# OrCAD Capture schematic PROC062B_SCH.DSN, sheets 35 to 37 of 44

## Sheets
35 34.SERDES & DISPLAY INTERFACE: size C; title: SERDES & DISPLAY INTERFACE
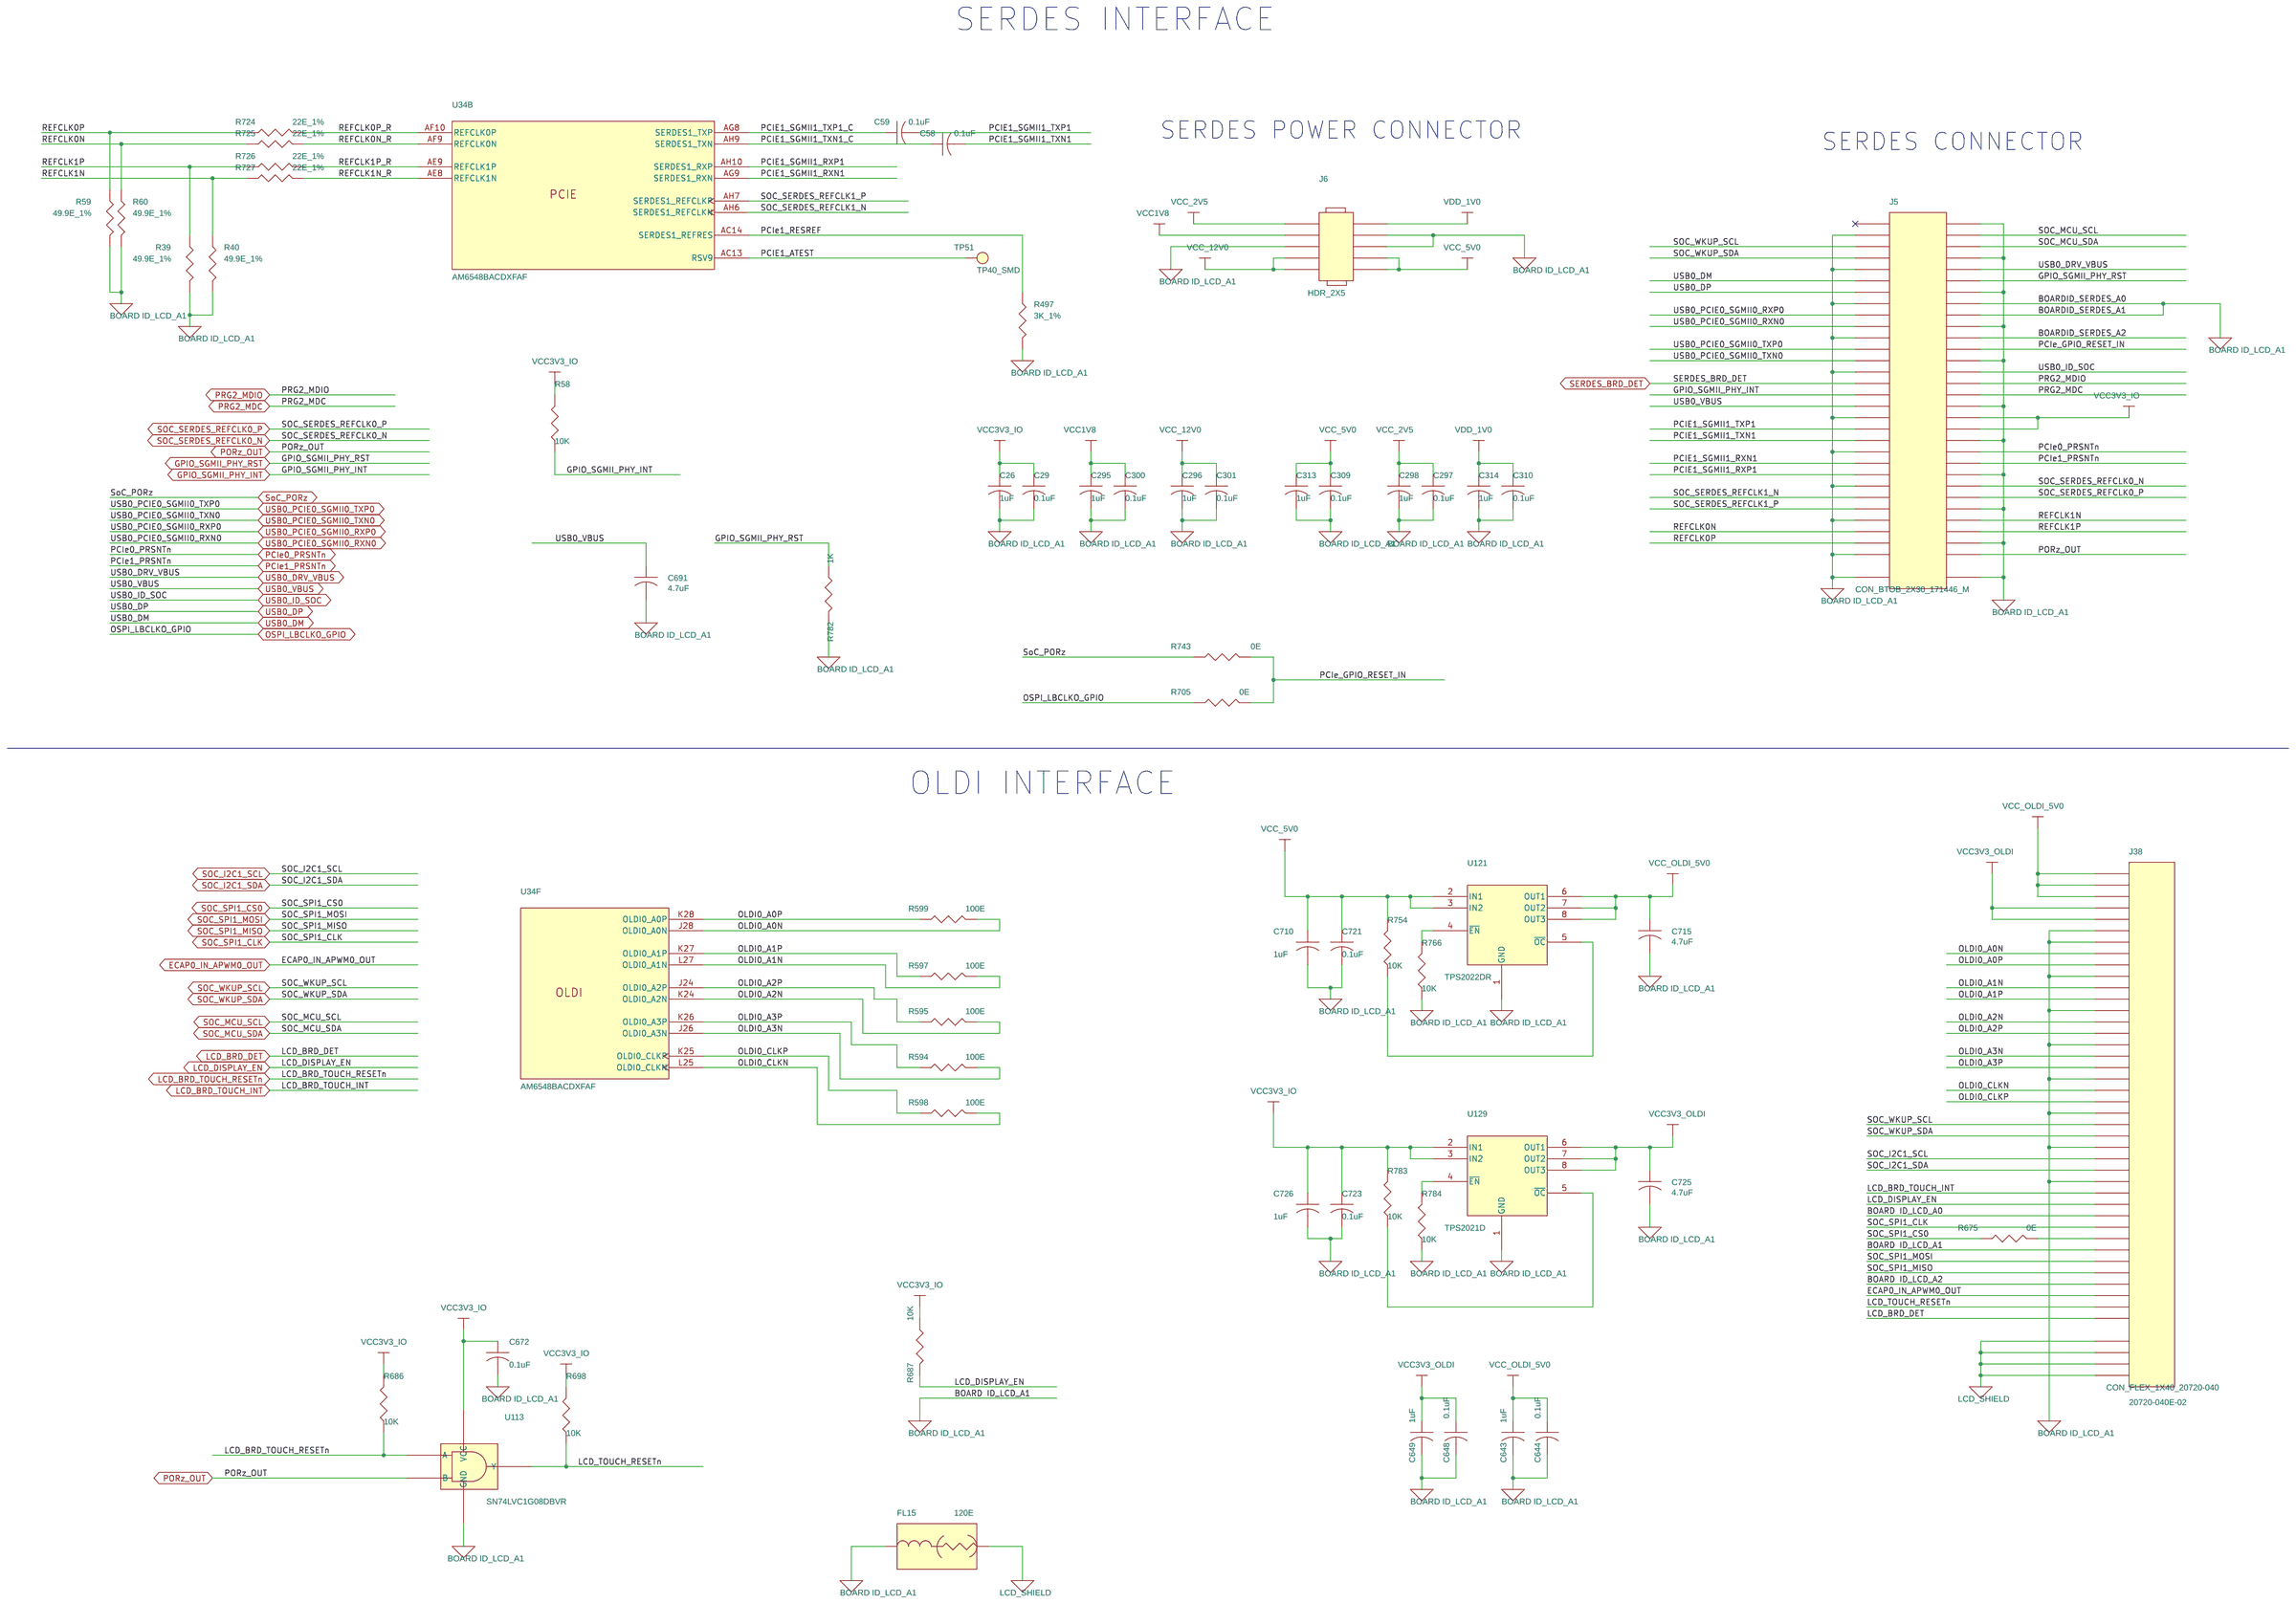
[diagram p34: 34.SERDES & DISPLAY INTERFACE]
36 36.ETHERNET PHY CLOCK BUFFER: size C; title: ETHERNET PHY CLOCK GENERATOR
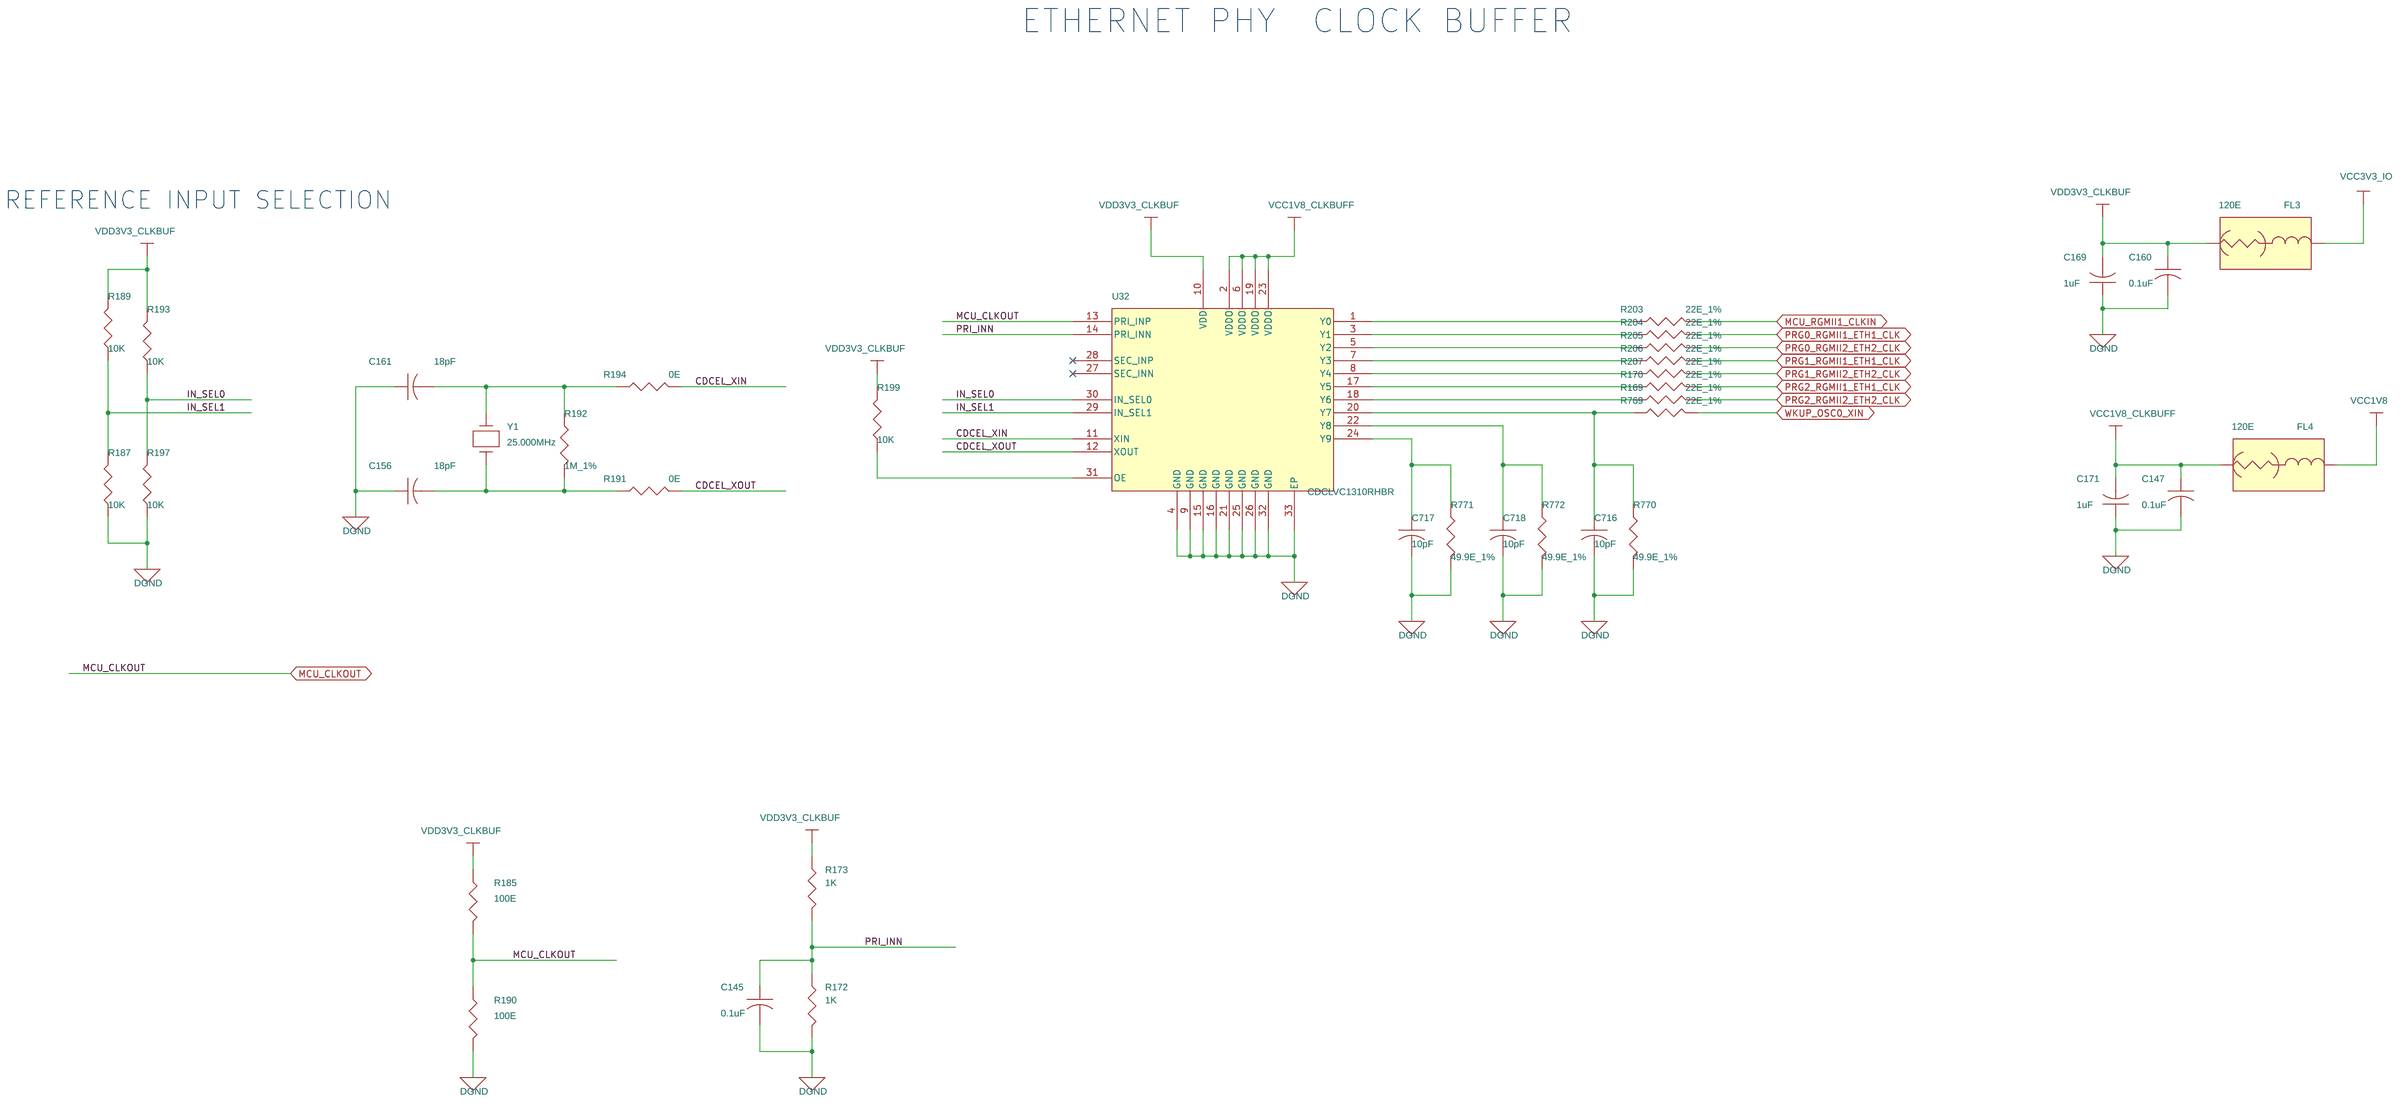
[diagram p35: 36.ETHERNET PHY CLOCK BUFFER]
37 37. ETHERNET LED's: size C; title: ETHERNET LEDs
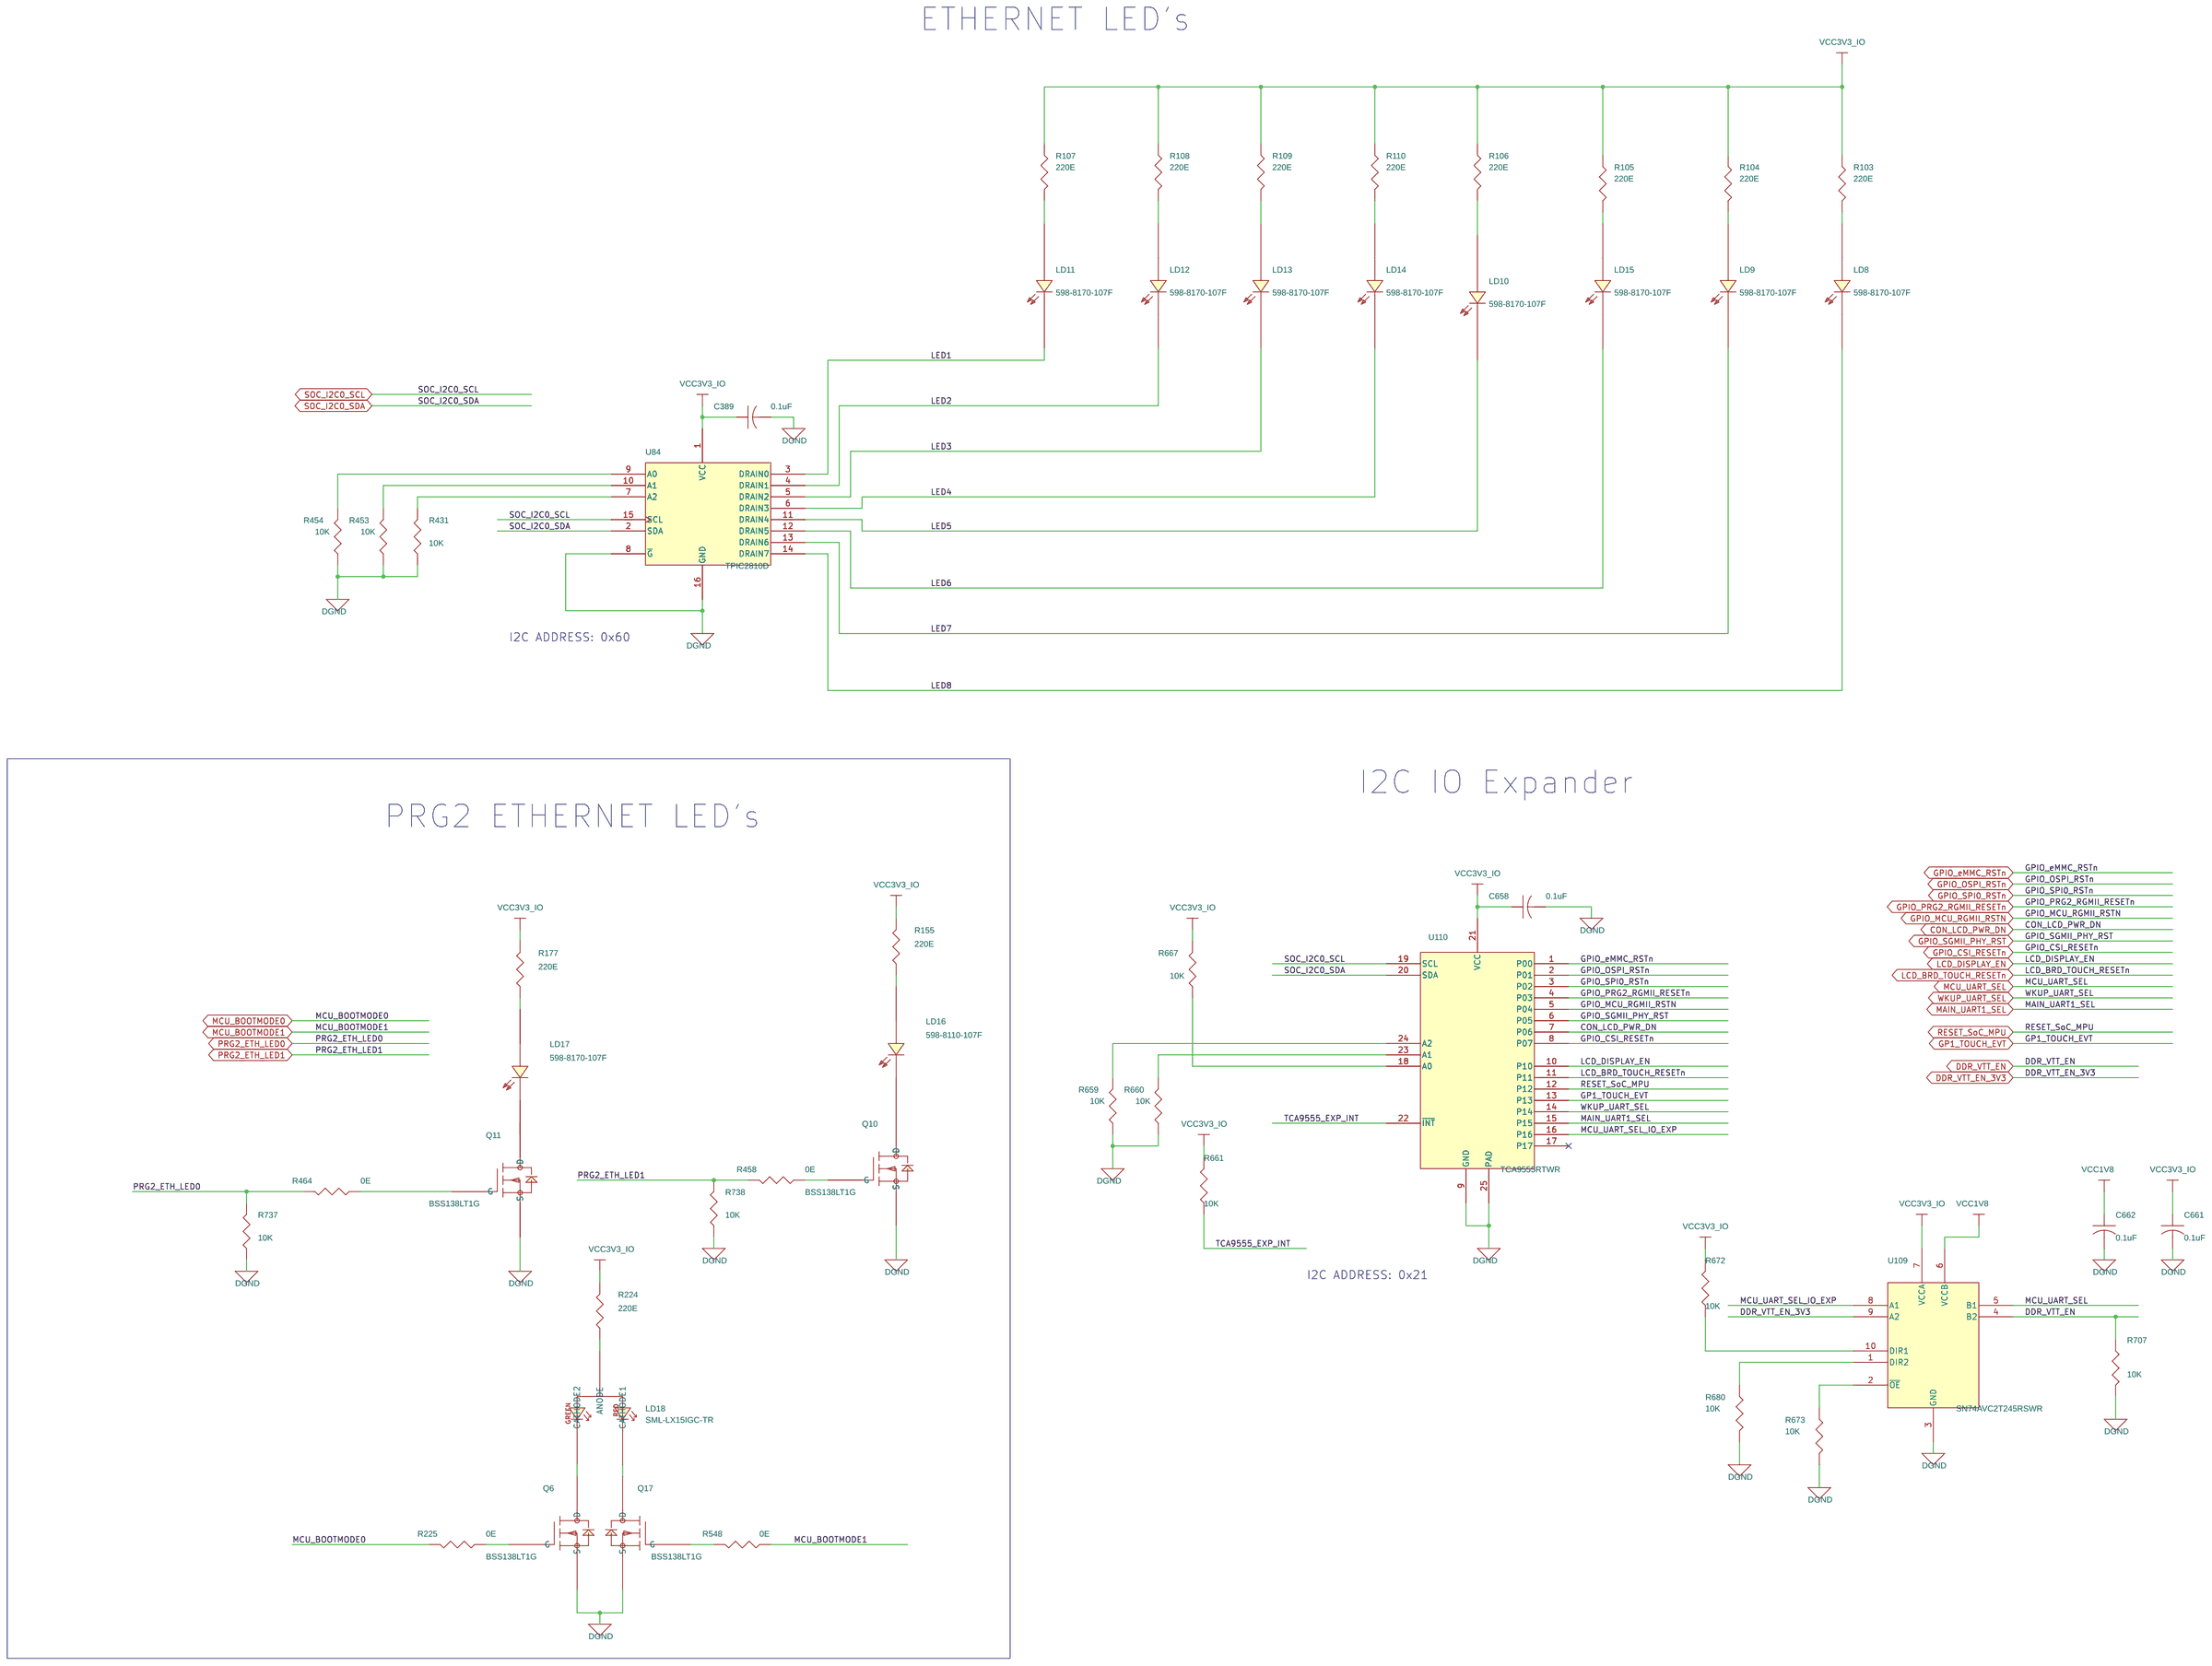
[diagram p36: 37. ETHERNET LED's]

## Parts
sheet 16. DDR4 ECC & TERMINATIONS
U34  AM6548BACDXFAF  [BGA784_31-49_910X910_1-7]  (sections A,B,C,D,E,F,G,H,I,J,K,L,M,N,O,P,Q,R,S)
sheet 34.SERDES & DISPLAY INTERFACE
C26  1uF  [CAP0402_0-75]
C29  0.1uF  [CAP0201_0-5]
C58  0.1uF  [CAP0402_0-75]
C59  0.1uF  [CAP0402_0-75]
C295  1uF  [CAP0402_0-75]
C296  1uF  [CAP0402_0-75]
C297  0.1uF  [CAP0201_0-5]
C298  1uF  [CAP0402_0-75]
C300  0.1uF  [CAP0201_0-5]
C301  0.1uF  [CAP0201_0-5]
C309  0.1uF  [CAP0201_0-5]
C310  0.1uF  [CAP0201_0-5]
C313  1uF  [CAP0402_0-75]
C314  1uF  [CAP0402_0-75]
C643  1uF  [CAP0402_0-75]
C644  0.1uF  [CAP0201_0-5]
C648  0.1uF  [CAP0201_0-5]
C649  1uF  [CAP0402_0-75]
C672  0.1uF  [CAP0201_0-5]
C691  4.7uF  [CAP0402_0-75]
C710  1uF  [CAP0402_0-75]
C715  4.7uF  [CAP0402_0-75]
C721  0.1uF  [CAP0201_0-5]
C723  0.1uF  [CAP0201_0-5]
C725  4.7uF  [CAP0402_0-75]
C726  1uF  [CAP0402_0-75]
FL15  120E  [EMIFIL_BLM15A_0402_0-6]
J5  CON_BTOB_2X30_171446_M  [CON_BTOB2X30_171446_P_S_S_5-5]
J6  HDR_2X5  [HDR_2X5_TFC-105-01-D-A_S_T_5-6]
J38  CON_FLEX_1X40_20720-040  [CON_FLEX1X40_20720-040_S_R_S_2]
R39  49.9E_1%  [RES0201_0-5]
R40  49.9E_1%  [RES0201_0-5]
R58  10K  [RES0402_0-5]
R59  49.9E_1%  [RES0201_0-5]
R60  49.9E_1%  [RES0201_0-5]
R497  3K_1%  [RES0402_0-5]
R594  100E  [RES0201]
R595  100E  [RES0201]
R597  100E  [RES0201]
R598  100E  [RES0201]
R599  100E  [RES0201]
R675  0E  [RES0402_0-5]
R686  10K  [RES0402_0-5]
R687  10K  [RES0402_0-5]
R698  10K  [RES0402_0-5]
R705  0E  [RES0402_0-5]
R724  22E_1%  [RES0402]
R725  22E_1%  [RES0402]
R726  22E_1%  [RES0402]
R727  22E_1%  [RES0402]
R743  0E  [RES0402_0-5]
R754  10K  [RES0402_0-5]
R766  10K  [RES0402_0-5]
R782  1K  [RES0402]
R783  10K  [RES0402_0-5]
R784  10K  [RES0402_0-5]
TP51  TP40_SMD  [TP40_SMD]
U113  SN74LVC1G08DBVR  [SOT23-5]
U121  TPS2022DR  [SOIC8_1-8]
U129  TPS2021D  [SOIC8]
sheet 36.ETHERNET PHY CLOCK BUFFER
C145  0.1uF  [CAP0201_0-5]
C147  0.1uF  [CAP0201_0-5]
C156  18pF  [CAP0402_0-75]
C160  0.1uF  [CAP0201_0-5]
C161  18pF  [CAP0402_0-75]
C169  1uF  [CAP0402_0-75]
C171  1uF  [CAP0402_0-75]
C716  10pF  [CAP0402_0-75]
C717  10pF  [CAP0402_0-75]
C718  10pF  [CAP0402_0-75]
FL3  120E  [EMIFIL_BLM15A_0402_0-6]
FL4  120E  [EMIFIL_BLM15A_0402_0-6]
R169  22E_1%  [RES0402]
R170  22E_1%  [RES0402]
R172  1K  [RES0201]
R173  1K  [RES0201]
R185  100E  [RES0402_0-5]
R187  10K  [RES0402_0-5]
R189  10K  [RES0402_0-5]
R190  100E  [RES0402_0-5]
R191  0E  [RES0402_0-5]
R192  1M_1%  [RES0402]
R193  10K  [RES0402_0-5]
R194  0E  [RES0402_0-5]
R197  10K  [RES0402_0-5]
R199  10K  [RES0402_0-5]
R203  22E_1%  [RES0402]
R204  22E_1%  [RES0402]
R205  22E_1%  [RES0402]
R206  22E_1%  [RES0402]
R207  22E_1%  [RES0402]
R769  22E_1%  [RES0402]
R770  49.9E_1%  [RES0201]
R771  49.9E_1%  [RES0201]
R772  49.9E_1%  [RES0201]
U32  CDCLVC1310RHBR  [QFN32_19-68_200X200_1]
Y1  25.000MHz  [XTAL_ABM3_205X130_SMD_1-4]
sheet 37. ETHERNET LED's
C389  0.1uF  [CAP0201_0-5]
C658  0.1uF  [CAP0201_0-5]
C661  0.1uF  [CAP0201_0-5]
C662  0.1uF  [CAP0201_0-5]
LD8  598-8170-107F  [LED_0805_0-7]
LD9  598-8170-107F  [LED_0805_0-7]
LD10  598-8170-107F  [LED_0805_0-7]
LD11  598-8170-107F  [LED_0805_0-7]
LD12  598-8170-107F  [LED_0805_0-7]
LD13  598-8170-107F  [LED_0805_0-7]
LD14  598-8170-107F  [LED_0805_0-7]
LD15  598-8170-107F  [LED_0805_0-7]
LD16  598-8110-107F  [LED_0805]
LD17  598-8170-107F  [LED_0805_0-7]
LD18  SML-LX15IGC-TR  [LED3_SML-LX15IGC_120X120_SMD_1]
Q6  BSS138LT1G  [SOT23-123]
Q10  BSS138LT1G  [SOT23-123]
Q11  BSS138LT1G  [SOT23-123]
Q17  BSS138LT1G  [SOT23-123]
R103  220E  [RES0402_0-5]
R104  220E  [RES0402_0-5]
R105  220E  [RES0402_0-5]
R106  220E  [RES0402_0-5]
R107  220E  [RES0402_0-5]
R108  220E  [RES0402_0-5]
R109  220E  [RES0402_0-5]
R110  220E  [RES0402_0-5]
R155  220E  [RES0402_0-5]
R177  220E  [RES0402_0-5]
R224  220E  [RES0402_0-5]
R225  0E  [RES0402_0-5]
R431  10K  [RES0402_0-5]
R453  10K  [RES0402_0-5]
R454  10K  [RES0402_0-5]
R458  0E  [RES0402_0-5]
R464  0E  [RES0402_0-5]
R548  0E  [RES0402_0-5]
R659  10K  [RES0402_0-5]
R660  10K  [RES0402_0-5]
R661  10K  [RES0402_0-5]
R667  10K  [RES0402_0-5]
R672  10K  [RES0402_0-5]
R673  10K  [RES0402_0-5]
R680  10K  [RES0402_0-5]
R707  10K  [RES0402_0-5]
R737  10K  [RES0402_0-5]
R738  10K  [RES0402_0-5]
U84  TPIC2810D  [SOIC16_1-8]
U109  SN74AVC2T245RSWR  [QFN10_15-74_75X60]
U110  TCA9555RTWR  [QFN24_19-68_165X165]

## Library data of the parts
U34 = AM654X_BGA784: IC AM65X MICRO CONTROLLER UNIT BGA784; Chkd/date: ALVY/010721; Crtd /date: MANIRAJA/010721; Custom_Duty: 15%; Customs_HS_Code: 85423100; Distributor_name: NA; Distributor_part_number: NA; Footprint Path: Y:\MIS_DATABASE\Library\ALTIUM_TOOL\PCB_FOOTPRINTS\Altium_Footprint_Lib.PcbLib; Height: 1.63MM; Library Path: Y:\MIS_DATABASE\Library\ALTIUM_TOOL\SCHEMATICS_PARTS\MS_MICROCONTROLLER_Library.schlib; Mfr_name: TEXAS INSTRUMENTS; Mistral Part No: 141221070001; Package: BGA784; Part_type: ICS\DIGITAL\MICROCONTROLLER; Project: TI_AM65X_CP; RoHS: NA; Temperature: NA; Tolerance: NA; Voltage: NA; Wattage: NA; Weight: NA; Datasheet: Y:\MIS_DATABASE\DATASHEETS\ICS\DIGITAL\MICROCONTROLLER\MAXWELLM4.PDF
C26 C169 C171 C295 C296 C298 C313 C314 C643 C649 C710 C726 = CAP: CAP CERAMIC 1uF 16V 20% X5R 0402; Chkd/date: MANIRAJA/150218; Crtd /date: ALVY/150218; Custom_Duty: 15%; Customs_HS_Code: 85322990; Distributor_name: DIGIKEY; Distributor_part_number: 587-5514-1-ND; Footprint Path: Y:\MIS_DATABASE\Library\ALTIUM_TOOL\PCB_FOOTPRINTS\Altium_Footprint_Lib.PcbLib; Height: 0.55MM; Library Path: Y:\MIS_DATABASE\Library\ALTIUM_TOOL\SCHEMATICS_PARTS\MS_DISCRETE_Library.schlib; Mfr_name: TAIYO YUDEN; Mfr_part_number: EMK105BJ105MV-F; Mistral Part No: 120018020006-R; Package: 0402; Part_type: CAPACITORS\CERAMIC; Project: TI_MAXIE_CPB; RoHS: RoHS; Temperature: -55°C+85°C; Tolerance: 20%; Voltage: 16V; Wattage: NA; Weight: 0.65mg; Datasheet: Y:\MIS_DATABASE\DATASHEETS\CAPACITORS\EMK105BJ105MV-F.PDF
C29 C145 C147 C160 C297 C300 C301 C309 C310 C389 C644 C648 C658 C661 C662 C672 C721 C723 = CAP: CAP CERAMIC 0.1uF 16V 10% X5R 0201; Chkd/date: MANIRAJA/120218; Crtd /date: MANIRAJA/120218; Custom_Duty: 15%; Customs_HS_Code: 85322990; Distributor_name: DIGIKEY; Distributor_part_number: 490-16742-1-ND; Height: 0.33MM; Mfr_name: MURATA; Mfr_part_number: GRM033R61C104KE84J; Mistral Part No: 120009030072-R; Package: 0201; Part_type: CAPACITORS\CERAMIC; Project: TI_MAXIE_CPB; RoHS: RoHS; Temperature: -55°C+85°C; Tolerance: 10%; Voltage: 16V; Wattage: NA; Weight: 0.33mg; Datasheet: Y:\MIS_DATABASE\DATASHEETS\CAPACITORS\GRM033R61C104KE84.PDF
C58 C59 = CAP: CAP CERAMIC 0.1uF 16V 10% X7R 0402; Chkd/date: VASANTHA/300115; Crtd /date: USMAN/111012; Custom_Duty: 15%; Customs_HS_Code: 85322990; Distributor_name: MOUSER; Distributor_part_number: 581-530L104KT16T; Footprint Path: Y:\MIS_DATABASE\Library\ALTIUM_TOOL\PCB_FOOTPRINTS\Altium_Footprint_Lib.PcbLib; Height: 0.61MM; Library Path: Y:\MIS_DATABASE\Library\ALTIUM_TOOL\SCHEMATICS_PARTS\MS_DISCRETE_Library.schlib; Mfr_name: ATC; Mfr_part_number: ATC530L104KT16T; Mistral Part No: 120009030060-R; Package: 0402; Part_type: CAPACITORS\CERAMIC; Project: DTRM; Remarks: Distributor PART ADDED; RoHS: RoHS; Temperature: -55°C+125°C; Tolerance: 10%; Voltage: 16V; Wattage: NA; Weight: 0.65mg; Datasheet: Y:\MIS_DATABASE\DATASHEETS\CAPACITORS\ATC530.PDF
C691 C715 C725 = CAP: CAP CERAMIC 4.7uF 10V 20% X5R 0402; Chkd/date: MANIRAJA/230118; Crtd /date: MANIRAJA/230118; Custom_Duty: 15%; Customs_HS_Code: 85322990; Distributor_name: DIGIKEY; Distributor_part_number: 478-10791-1-ND; Height: 0.71MM; Mfr_name: AVX CORPORATION; Mfr_part_number: 0402ZD475MAT2A; Mistral Part No: 120012060002-R; Package: 0402; Part_type: CAPACITORS\CERAMIC; Project: TI_MAXIE_CPB; RoHS: RoHS; Temperature: -55°C+85°C; Tolerance: 20%; Voltage: 10V; Wattage: NA; Weight: 0.65mg; Datasheet: Y:\MIS_DATABASE\DATASHEETS\CAPACITORS\AVX_MLC.PDF
FL3 FL4 FL15 = EMIFILTER_IND: FERRITE CHIP 120E 1.3A 0402; Chkd/date: VASANTHA/010117; Crtd /date: CHAITHANYA/150312; Custom_Duty: 24%; Customs_HS_Code: 85437099; Distributor_name: DIGIKEY; Distributor_part_number: 490-5203-1-ND; Footprint Path: Y:\MIS_DATABASE\Library\ALTIUM_TOOL\PCB_FOOTPRINTS\Altium_Footprint_Lib.PcbLib; Height: 0.55MM; Library Path: Y:\MIS_DATABASE\Library\ALTIUM_TOOL\SCHEMATICS_PARTS\MS_FILTER_Library.schlib; Mfr_name: MURATA; Mfr_part_number: BLM15PD121SN1; Mistral Part No: 130012030043-R; Package: 0402; Part_type: MISC\FILTER; Project: GEN_3-8; RoHS: RoHS; Temperature: -55°C+125°C; Tolerance: 25%; Voltage: NA; Wattage: NA; Weight: 0.65mg; Datasheet: Y:\MIS_DATABASE\DATASHEETS\DISCRETES\INDUCTORS\BLM18K-SERIES.PDF
J5 = CON_BTOB_30X2_171446: CON BTOB 2X30 0.80MM PITCH MALE ST SMD; Chkd/date: MANIRAJA/051017; Crtd /date: MANIRAJA/051017; Custom_Duty: 24%; Customs_HS_Code: 85369090; Distributor_name: DIGIKEY; Distributor_part_number: 1714461114-ND; Height: 5.50MM; Mfr_name: MOLEX; Mfr_part_number: 171446-1114; Mistral Part No: 150017100005-R; Package: SMD; Part_type: CONNECTOR\BTOB; Project: TI_MAXIE_CPB; RoHS: RoHS; Temperature: -40°C+105°C; Tolerance: NA; Voltage: NA; Wattage: NA; Weight: 526mg; Datasheet: Y:\MIS_DATABASE\DATASHEETS\CONNECTORS\171446-SER.PDF
J6 = HEADER_5X2: CON HDR 2X5 1.27MM PITCH ST TH; Chkd/date: VASANTHA/181017; Crtd /date: VASANTHA/181017; Custom_Duty: 24%; Customs_HS_Code: 85369090; Distributor_name: NA; Distributor_part_number: NA; Height: 5.59MM; Mfr_name: SAMTEC; Mfr_part_number: TFC-105-01-L-D-A; Mistral Part No: 150017100027-R; Package: THRU-HOLE; Part_type: CONNECTOR\HEADERS; Project: TI_MAXIE_CPB; RoHS: RoHS; Temperature: -55°C+125°C; Tolerance: NA; Voltage: NA; Wattage: NA; Weight: NA; Datasheet: Y:\MIS_DATABASE\DATASHEETS\CONNECTORS\TFC-TH-SERIES.PDF
J38 = CON_FLEX_40X1_SH4: CON FPC 1X40 0.50MM PITCH RT SMD; Chkd/date: MANIRAJA/121017; Crtd /date: MANIRAJA/121017; Custom_Duty: 24%; Customs_HS_Code: 85369090; Distributor_name: NA; Distributor_part_number: NA; Height: 2.00MM; Mfr_name: IPEX; Mfr_part_number: 20720-040E-02; Mistral Part No: 150017100021-R; Package: SMD; Part_type: CONNECTOR\FPC; Project: TI_MAXIE_CPB; RoHS: RoHS; Temperature: -40°C+105°C; Tolerance: NA; Voltage: NA; Wattage: NA; Weight: NA; Datasheet: Y:\MIS_DATABASE\DATASHEETS\CONNECTORS\20720-0XX.PDF
R39 R40 R59 R60 = RESISTOR: RES 49.9E 1/20W 1% AUTO 0201; Chkd/date: MANIRAJA/310818; Crtd /date: MANIRAJA/310818; Custom_Duty: 15%; Customs_HS_Code: 85332119; Distributor_name: DIGIKEY; Distributor_part_number: YAG5218CT-ND; Footprint Path: Y:\MIS_DATABASE\Library\ALTIUM_TOOL\PCB_FOOTPRINTS\Altium_Footprint_Lib.PcbLib; Height: 0.26MM; Library Path: Y:\MIS_DATABASE\Library\ALTIUM_TOOL\SCHEMATICS_PARTS\MS_DISCRETE_Library.schlib; Mfr_name: YAGEO AMERICA; Mfr_part_number: AC0201FR-0749R9L; Mistral Part No: 110018080018-R; Package: 0201; Part_type: RESISTORS\FIXED; Project: TI_MAXIE_CPB; RoHS: RoHS; Temperature: -55°C+155°C; Tolerance: 1%; Voltage: NA; Wattage: 1/20W; Weight: NA; Datasheet: Y:\MIS_DATABASE\DATASHEETS\RESISTORS\AC_SER_JUN17.PDF
R58 R187 R189 R193 R197 R199 R431 R453 R454 R659-R661 R667 R672 R673 R680 R686 R687 R698 R707 R737 R738 R754 R766 R783 R784 = RESISTOR: RES 10K 1/16W 5% 0402; Chkd/date: VASANTHA/061216; Crtd /date: MAZHAR/230805; Custom_Duty: 15%; Customs_HS_Code: 85332119; Distributor_name: DIGIKEY; Distributor_part_number: 311-10KJRCT-ND; Footprint Path: Y:\MIS_DATABASE\Library\ALTIUM_TOOL\PCB_FOOTPRINTS\Altium_Footprint_Lib.PcbLib; Height: 0.40MM; Library Path: Y:\MIS_DATABASE\Library\ALTIUM_TOOL\SCHEMATICS_PARTS\MS_DISCRETE_Library.schlib; Mfr_name: YAGEO AMERICA; Mfr_part_number: RC0402JR-0710KL; Mistral Part No: 110009030208-R; Package: 0402; Part_type: RESISTORS\FIXED; Project: HSE; RoHS: Pb-Free; Temperature: -55°C+155°C; Tolerance: 5%; Voltage: NA; Wattage: 1/16W; Weight: 0.65mg; Datasheet: Y:\MIS_DATABASE\DATASHEETS\RESISTORS\YAGEO-RC0402.PDF
R497 = RESISTOR: RES 3K 1/16W 1% 0402; Chkd/date: MANIRAJA/101117; Crtd /date: MANIRAJA/101117; Custom_Duty: 15%; Customs_HS_Code: 85332119; Distributor_name: DIGIKEY; Distributor_part_number: 311-3KLRCT-ND; Height: 0.40MM; Mfr_name: YAGEO AMERICA; Mfr_part_number: RC0402FR-073KL; Mistral Part No: 110017110004-R; Package: 0402; Part_type: RESISTORS\FIXED; Project: TI_SVB_MAXWELL_DUT; RoHS: RoHS; Temperature: -55°C+155°C; Tolerance: 1%; Voltage: NA; Wattage: 1/16W; Weight: 0.65mg; Datasheet: Y:\MIS_DATABASE\DATASHEETS\RESISTORS\YAGEO.PDF
R594 R595 R597-R599 = RESISTOR: RES 100E 1/20W 5% 0201; Chkd/date: SUHAS/280910; Crtd /date: MUDDU/100710; Custom_Duty: 15%; Customs_HS_Code: 85332119; Distributor_name: NA; Distributor_part_number: NA; Height: 0.30MM; Mfr_name: NIC COMPONENTS; Mfr_part_number: NRC02J101TRF; Mistral Part No: 110010070060-R; Package: 0201; Part_type: RESISTORS\FIXED; Project: PB_BUGBASE; RoHS: RoHS; Temperature: -55°C+125°C; Tolerance: 5%; Voltage: 50V; Wattage: 1/20W; Weight: NA; Datasheet: Y:\MIS_DATABASE\DATASHEETS\RESISTORS\NRC SERIES.PDF
R191 R194 R225 R458 R464 R548 R675 R705 R743 = RESISTOR: RES 0E 1/16W 0402; Chkd/date: VASANTHA/201216; Crtd /date: MUDDU/190810; Custom_Duty: 15%; Customs_HS_Code: 85332119; Distributor_name: DIGIKEY; Distributor_part_number: 541-0.0JCT-ND; Footprint Path: Y:\MIS_DATABASE\Library\ALTIUM_TOOL\PCB_FOOTPRINTS\Altium_Footprint_Lib.PcbLib; Height: 0.40MM; Library Path: Y:\MIS_DATABASE\Library\ALTIUM_TOOL\SCHEMATICS_PARTS\MS_DISCRETE_Library.schlib; Mfr_name: VISHAY; Mfr_part_number: CRCW04020000Z0ED; Mistral Part No: 110010080019-P; Package: 0402; Part_type: RESISTORS\FIXED; Project: PB_BUGBASE; RoHS: Pb-Free; Temperature: -55°C+155°C; Tolerance: NA; Voltage: NA; Wattage: 1/16W; Weight: 0.65g/1000pcs; Datasheet: Y:\MIS_DATABASE\DATASHEETS\RESISTORS\CRCW0603.PDF
R724-R727 = RESISTOR: RES 22E 1/16W 1% 0402; Alternate_mfr_name_A: VISHAY; Alternate_mfr_part_number_A: CRCW040222R0FKED; Chkd/date: SUHAS/290910; Crtd /date: MAZHAR/090909; Cust_part_number: 4700-80047E; Custom_Duty: 15%; Customs_HS_Code: 85332119; Distributor_name: DIGIKEY; Distributor_name_A: DIGIKEY; Distributor_part_number: 311-22.0LRCT-ND; Distributor_part_number_A: 541-22.0LCT-ND; Height: 0.40MM; Mfr_name: YAGEO AMERICA; Mfr_part_number: RC0402FR-0722RL; Mistral Part No: 110009090004-P; Package: 0402; Part_type: RESISTORS\FIXED; Project: VMEFMCD; Remarks: In alternate datasheet it is RoHS COMPLIANT. Y:\MIS_DATABASE\DATASHEETS\RESISTORS\CRCW0402.PDF; RoHS: Pb-Free; Temperature: -55°C+155°C; Tolerance: 1%; Voltage: 50V; Wattage: 1/16W; Weight: 0.8g/1000pcs; Datasheet: Y:\MIS_DATABASE\DATASHEETS\RESISTORS\YAGEO-RC0402.PDF
R782 = RESISTOR: RES 1K 1/16W 5% 0402; Crtd /date: BAVISH/021210; Distributor_name: DIGIKEY; Distributor_part_number: 541-1.0KJCT-ND; Footprint Path: VALUE IS VAILABLE 2 TIMES; Height: 0.40MM; Mfr_name: VISHAY; Mfr_part_number: CRCW04021K00JNED; Mistral Part No: 110010120017-R; Package: 0402; Part_type: RESISTORS\FIXED; Project: TE4; RoHS: RoHS; Temperature: -55°C+155°C; Tolerance: 5%; Voltage: NA; Wattage: 1/16W; Weight: NA; Datasheet: Y:\MIS_DATABASE\DATASHEETS\RESISTORS\CRCW0603.PDF
TP51 = TESTPOINT: TESTPOINT CIR 40 SMD; Chkd/date: MAZHAR/190505; Crtd /date: MAZHAR/190505; Distributor_name: NA; Distributor_part_number: NA; Footprint Path: Y:\MIS_DATABASE\Library\ALTIUM_TOOL\PCB_FOOTPRINTS\Altium_Footprint_Lib.PcbLib; Height: NA; Library Path: Y:\MIS_DATABASE\Library\ALTIUM_TOOL\SCHEMATICS_PARTS\MS_DISCRETE_Library.schlib; MECHANICAL 3D STEP FILE: NA; Mfr_name: LOCAL; Mistral Part No: 130009030933; Package: SMD; Project: RAINIER-3; RoHS: NA; Temperature: NA; Tolerance: NA; Voltage: NA; Wattage: NA; Weight: NA; Datasheet: NA
U113 = SN74LVC1G08DBVR_SOT23-5: IC SINGLE 2-INPUT POSITIVE AND GATE SOT23-5; Chkd/date: SHREESHAIL/270906; Crtd /date: MAZHAR/270906; Custom_Duty: 15%; Customs_HS_Code: 85423100; Distributor_name: DIGIKEY; Distributor_part_number: 296-11601-1-ND; Height: 1.45MM; Mfr_name: TEXAS INSTRUMENTS; Mistral Part No: 141009030228-R; Part_type: ICS\DIGITAL\GATES; Project: SVDO_RMB_MMA; RoHS: Sb/ Br FREE; Datasheet: Y:\MIS_DATABASE\DATASHEETS\ICS\DIGITAL\GATES\SN74LVC1G08.PDF
U121 = TPS2021D_SOIC8: IC 1.5A POWER DISTRIBUTION SWITCH SOIC8; Chkd/date: MANIRAJA/010719; Crtd /date: MANIRAJA/010719; Custom_Duty: 15%; Customs_HS_Code: 85423100; Distributor_name: DIGIKEY; Distributor_part_number: 296-38286-1-ND; Footprint Path: Y:\MIS_DATABASE\Library\ALTIUM_TOOL\PCB_FOOTPRINTS\Altium_Footprint_Lib.PcbLib; Height: 1.75MM; Library Path: Y:\MIS_DATABASE\Library\ALTIUM_TOOL\SCHEMATICS_PARTS\MS_MISCPOWER_Library.schlib; Mfr_name: TEXAS INSTRUMENTS; Mistral Part No: 142019070001-R; Package: SOIC8; Part_type: ICS\POWER; Project: TI_MAXIE_CPB; RoHS: RoHS; Temperature: -40°C+85°C; Tolerance: NA; Voltage: NA; Wattage: NA; Weight: 72.6mg; Datasheet: Y:\MIS_DATABASE\DATASHEETS\ICS\POWER\TPS2022.PDF
U129 = TPS2021D_SOIC8: IC POWER DISTRIBUTION SWITCH SOIC8; Chkd/date: SHREESHAIL/180607; Crtd /date: MAZHAR/280806; Custom_Duty: 15%; Customs_HS_Code: 85423100; Distributor_name: DIGIKEY; Distributor_part_number: 296-2561-5-ND; Height: 1.75MM; Mfr_name: TEXAS INSTRUMENTS; Mistral Part No: 142009030022-R; Part_type: ICS\POWER; Project: SVDO_RMB_MMA; RoHS: Sb/ Br FREE; Datasheet: Y:\MIS_DATABASE\DATASHEETS\ICS\POWER\TPS2021.PDF
C156 C161 = CAP: CAP CERAMIC 18pF 50V 5% C0G(NP0) 0402; Chkd/date: MANIRAJA/070220; Crtd /date: ALVY/070220; Custom_Duty: 15%; Customs_HS_Code: 85322990; Distributor_name: DIGIKEY; Distributor_part_number: 399-8952-1-ND; Footprint Path: Y:\MIS_DATABASE\Library\ALTIUM_TOOL\PCB_FOOTPRINTS\Altium_Footprint_Lib.PcbLib; Height: 0.55MM; Library Path: Y:\MIS_DATABASE\Library\ALTIUM_TOOL\SCHEMATICS_PARTS\MS_DISCRETE_Library.schlib; Mfr_name: KEMET; Mfr_part_number: C0402C180J5GAC7867; Mistral Part No: 120011090034-R; Package: 0402; Part_type: CAPACITORS\CERAMIC; Project: TI_MAXIE_CPB; RoHS: RoHS; Temperature: -55°C+125°C; Tolerance: 5%; Voltage: 50V; Wattage: NA; Weight: 0.65mg; Datasheet: Y:\MIS_DATABASE\DATASHEETS\CAPACITORS\KEMET-C0G_SERIES.PDF
C716-C718 = CAP: CAP CERAMIC 10pF 16V 5% C0G(NP0) 0402; Chkd/date: MANIRAJA/100918; Crtd /date: ALVY/100918; Custom_Duty: 15%; Customs_HS_Code: 85322990; Distributor_name: DIGIKEY; Distributor_part_number: 732-7441-1-ND; Footprint Path: Y:\MIS_DATABASE\Library\ALTIUM_TOOL\PCB_FOOTPRINTS\Altium_Footprint_Lib.PcbLib; Height: 0.55MM; Library Path: Y:\MIS_DATABASE\Library\ALTIUM_TOOL\SCHEMATICS_PARTS\MS_DISCRETE_Library.schlib; Mfr_name: WURTH ELECTRONICS; Mfr_part_number: 885012005025; Mistral Part No: 120018030015-R; Package: 0402; Part_type: CAPACITORS\CERAMIC; Project: SMART-M_SCRIPTALK_PB; RoHS: RoHS; Temperature: -55°C+125°C; Tolerance: 5%; Voltage: 16V; Wattage: NA; Weight: 0.65mg; Datasheet: Y:\MIS_DATABASE\DATASHEETS\CAPACITORS\885012005025.PDF
R169 R170 R203-R207 R769 = RESISTOR: RES 22E 1/16W 1% 0402; Alternate_mfr_name_A: VISHAY; Alternate_mfr_part_number_A: CRCW040222R0FKED; Chkd/date: SUHAS/290910; Crtd /date: MAZHAR/090909; Cust_part_number: 4700-80047E; Custom_Duty: 15%; Customs_HS_Code: 85332119; Distributor_name: DIGIKEY; Distributor_name_A: DIGIKEY; Distributor_part_number: 311-22.0LRCT-ND; Distributor_part_number_A: 541-22.0LCT-ND; Height: 0.40MM; Mfr_name: YAGEO AMERICA; Mfr_part_number: RC0402FR-0722RL; Mistral Part No: 110009090004-P; Package: 0402; Part_type: RESISTORS\FIXED; Project: VMEFMCD; Remarks: In alternate datasheet it is RoHS COMPLIANT. Y:\MIS_DATABASE\DATASHEETS\RESISTORS\CRCW0402.PDF; RoHS: Pb-Free; SIGNAL_MODEL: RESISTOR_RES0402_22E_22E; Temperature: -55°C+155°C; Tolerance: 1%; Voltage: 50V; Wattage: 1/16W; Weight: 0.8g/1000pcs; Datasheet: Y:\MIS_DATABASE\DATASHEETS\RESISTORS\YAGEO-RC0402.PDF
R172 R173 = RESISTOR: RES 1K 1/20W 5% 0201; Chkd/date: JEBRAN/110815; Crtd /date: JEBRAN/110815; Custom_Duty: 15%; Customs_HS_Code: 85332119; Distributor_name: DIGIKEY; Distributor_part_number: 541-1.00KAABCT-ND; Height: 0.28MM; Mfr_name: VISHAY; Mfr_part_number: CRCW02011K00FKED; Mistral Part No: 110015080014-R; Package: 0201; Part_type: RESISTORS\FIXED; Project: OCTASIC_3000; RoHS: RoHS; Temperature: -55°C+155°C; Tolerance: 5%; Voltage: NA; Wattage: 1/20W; Weight: NA; Datasheet: Y:\MIS_DATABASE\DATASHEETS\RESISTORS\CRCW0201.PDF
R185 R190 = RESISTOR: RES 100E 1/16W 5% 0402; Chkd/date: MANIRAJA/230817; Crtd /date: MANIRAJA/230817; Custom_Duty: 15%; Customs_HS_Code: 85332119; Distributor_name: DIGIKEY; Distributor_part_number: 541-100JCT-ND; Height: 0.40MM; Mfr_name: VISHAY; Mfr_part_number: CRCW0402100RJNED; Mistral Part No: 110009030164-R; Package: 0402; Part_type: RESISTORS\FIXED; Project: TI_MAXIE_CPB; RoHS: RoHS; Temperature: -55°C+155°C; Tolerance: 5%; Voltage: NA; Wattage: 1/16W; Weight: 0.65mg; Datasheet: Y:\MIS_DATABASE\DATASHEETS\RESISTORS\CRCW0603.PDF
R192 = RESISTOR: RES 1M 1/16W 1% 0402; Chkd/date: VASANTHA/200614; Crtd /date: NAVEED/170614; Custom_Duty: 15%; Customs_HS_Code: 85332119; Distributor_name: DIGIKEY; Distributor_part_number: RMCF0402FT1M00CT-ND; Footprint Path: Y:\MIS_DATABASE\Library\ALTIUM_TOOL\PCB_FOOTPRINTS\Altium_Footprint_Lib.PcbLib; Height: 0.40MM; Library Path: Y:\MIS_DATABASE\Library\ALTIUM_TOOL\SCHEMATICS_PARTS\MS_DISCRETE_Library.schlib; Mfr_name: STACKPOLE ELECTRONICS; Mfr_part_number: RMCF0402FT1M00; Mistral Part No: 110014060045-R; Package: 0402; Part_type: RESISTORS\FIXED; Project: AEGIS_POM; RoHS: RoHS; Temperature: -55°C+155°C; Tolerance: 1%; Voltage: NA; Wattage: 1/16W; Weight: 0.57mg; Datasheet: Y:\MIS_DATABASE\DATASHEETS\RESISTORS\RMCF-SERIES1.PDF
R770-R772 = RESISTOR: RES 49.9E 1/20W 1% 0201; Chkd/date: MAZHAR/140709; Crtd /date: MAZHAR/300807; Custom_Duty: 15%; Customs_HS_Code: 85332119; Distributor_name: DIGIKEY; Distributor_part_number: P49.9ABCT-ND; Footprint Path: Y:\MIS_DATABASE\Library\ALTIUM_TOOL\PCB_FOOTPRINTS\Altium_Footprint_Lib.PcbLib; Height: 0.26MM; Library Path: Y:\MIS_DATABASE\Library\ALTIUM_TOOL\SCHEMATICS_PARTS\MS_DISCRETE_Library.schlib; Mfr_name: PANASONIC-ECG; Mfr_part_number: ERJ-1GEF49R9C; Mistral Part No: 110009030893-R; Package: 0201; Part_type: RESISTORS\FIXED; Project: V8TS; RoHS: RoHS; Tolerance: 1%; Wattage: 1/20W; Datasheet: Y:\MIS_DATABASE\DATASHEETS\RESISTORS\ERJ-1G.PDF
U32 = CDCLVC1310RHBR_VQFN32: IC LOW JITTER,LOW POWER CLK BUFFER LEVEL TRANSLATOR VQFN32; Chkd/date: MANIRAJA/061017; Crtd /date: MANIRAJA/061017; Custom_Duty: 15%; Customs_HS_Code: 85423100; Distributor_name: DIGIKEY; Distributor_part_number: 296-30105-1-ND; Height: 1.00MM; Mfr_name: TEXAS INSTRUMENTS; Mistral Part No: 141017100003-R; Package: VQFN32; Part_type: ICS\INTERFACE\LEVEL TRANSLATOR; Project: TI_MAXIE_CPB; RoHS: RoHS; Temperature: -40°C+85°C; Tolerance: NA; Voltage: NA; Wattage: NA; Weight: 72.2mg; Datasheet: Y:\MIS_DATABASE\DATASHEETS\ICS\INTERFACE\CDCLVC1310RHBR.PDF
Y1 = CRY: CRY 25.000MHz 18pF SMD; Chkd/date: VASANTHA/110316; Crtd /date: JEBRAN/090216; Custom_Duty: 24%; Customs_HS_Code: 85439000; Distributor_name: DIGIKEY; Distributor_part_number: CTX1175CT-ND; Footprint Path: Y:\MIS_DATABASE\Library\ALTIUM_TOOL\PCB_FOOTPRINTS\Altium_Footprint_Lib.PcbLib; Height: 1.35MM; Library Path: Y:\MIS_DATABASE\Library\ALTIUM_TOOL\SCHEMATICS_PARTS\MS_DISCRETE_Library.schlib; Mfr_name: CTS; Mfr_part_number: 445I23D25M00000; Mistral Part No: 130016020016-R; Package: SMD; Part_type: CRYSTAL; Project: PDI_MINIPCB; RoHS: RoHS; Temperature: -40°C+85°C; Tolerance: NA; Voltage: NA; Wattage: NA; Weight: 50mg; Datasheet: Y:\MIS_DATABASE\DATASHEETS\MISC\CRY_OSC\445.PDF
LD8-LD15 LD17 = LED_598-8170-107F: LED ALINGAP GREEN CLEAR 0805; Chkd/date: MANIRAJA/230817; Crtd /date: SARANYA/070514; Custom_Duty: 24%; Customs_HS_Code: 85437099; Distributor_name: DIGIKEY; Distributor_part_number: 350-2044-1-ND; Height: 0.70MM; Mfr_name: DIALIGHT; Mistral Part No: 130014050065-R; Package: 0805; Part_type: OPTO\LED; Project: AEGIS GP BETA2; RoHS: RoHS; Temperature: -30°C+85°C; Tolerance: NA; Voltage: NA; Wattage: NA; Weight: NA; Datasheet: Y:\MIS_DATABASE\DATASHEETS\DISCRETES\LEDS\598-SER.PDF
LD16 = LED_598-8170-107F: LED ALINGAP RED CLEAR 0805 SMD; Chkd/date: BALACHANDAR/160514; Crtd /date: SARANYA/070514; Custom_Duty: 24%; Customs_HS_Code: 85437099; Distributor_name: DIGIKEY; Distributor_part_number: 350-2038-1-ND; Height: 0.70MM; Mfr_name: DIALIGHT; Mistral Part No: 130014050069-R; Package: 0805; Part_type: OPTO\LED; Project: AEGIS GP BETA2; RoHS: RoHS; Temperature: NA; Tolerance: NA; Voltage: NA; Wattage: NA; Weight: NA; Datasheet: Y:\MIS_DATABASE\DATASHEETS\DISCRETES\LEDS\598-SER.PDF
LD18 = LED3_SML-LX15IGC: DIODE LED GREEN/RED SMD; Chkd/date: MANIRAJA/180917; Crtd /date: MANIRAJA/180917; Custom_Duty: 24%; Customs_HS_Code: 85439000; Distributor_name: DIGIKEY; Distributor_part_number: 67-2193-1-ND; Height: 1.00MM; Mfr_name: LUMEX; Mistral Part No: 130017090021-R; Package: SMD; Part_type: OPTO\LED; Project: TI_MAXIE_CPB; RoHS: RoHS; Temperature: -40°C+85°C; Tolerance: NA; Voltage: NA; Wattage: NA; Weight: NA; Datasheet: Y:\MIS_DATABASE\DATASHEETS\DISCRETES\LEDS\SML-LX15IGC.PDF
Q6 Q10 Q11 Q17 = MOSFET_BSS138LT1G: IC MOSFET N-CHANNEL 50V, SOT23-3; Chkd/date: VASANTHA/150416; Crtd /date: JEBRAN/060416; Custom_Duty: 15%; Customs_HS_Code: 85423100; Distributor_name: MOUSER; Distributor_part_number: 863-BSS138LT1G; Height: 1.11MM; Mfr_name: ON SEMICONDUCTOR; Mistral Part No: 142016040001-R; Package: SOT23-3; Part_type: ICS\POWER\MOSFET; Project: LRDE_ABCM; RoHS: RoHS; Temperature: -55°C+150°C; Tolerance: NA; Voltage: 50V; Wattage: NA; Weight: NA; Datasheet: Y:\MIS_DATABASE\DATASHEETS\DISCRETES\TRANSISTORS_FETS\BSS138LT1G.PDF
R103-R110 R155 R177 R224 = RESISTOR: RES 220E 1/16W 5% 0402; Chkd/date: VASANTHA/291216; Crtd /date: GEETHA/260406; Custom_Duty: 15%; Customs_HS_Code: 85332119; Distributor_name: DIGIKEY; Distributor_part_number: P220JCT-ND; Footprint Path: Y:\MIS_DATABASE\Library\ALTIUM_TOOL\PCB_FOOTPRINTS\Altium_Footprint_Lib.PcbLib; Height: 0.40MM; Library Path: Y:\MIS_DATABASE\Library\ALTIUM_TOOL\SCHEMATICS_PARTS\MS_DISCRETE_Library.schlib; Mfr_name: PANASONIC-ECG; Mfr_part_number: ERJ-2GEJ221X; Mistral Part No: 110009030506-R; Package: 0402; Part_type: RESISTORS\FIXED; Project: RED EYE; RoHS: RoHS; Temperature: -55°C+155°C; Tolerance: 5%; Voltage: NA; Wattage: 1/16W; Weight: 0.8g/1000pcs; Datasheet: Y:\MIS_DATABASE\DATASHEETS\RESISTORS\ERJ12.PDF
U84 = TPIC2810D_SOIC16: IC 8-BIT LED DRIVER WITH I2C INTERFACE SOIC16; Chkd/date: MANIRAJA/230817; Crtd /date: MANIRAJA/220817; Custom_Duty: 15%; Customs_HS_Code: 85423100; Distributor_name: DIGIKEY; Distributor_part_number: 296-13746-5-ND; Height: 1.75MM; Mfr_name: TEXAS INSTRUMENTS; Mistral Part No: 141017080026-R; Package: SOIC16; Part_type: ICS\INTERFACE; Project: TI_MAXIE_CPB; RoHS: RoHS; Temperature: -40°C+125°C; Tolerance: NA; Voltage: NA; Wattage: NA; Weight: NA; Datasheet: Y:\MIS_DATABASE\DATASHEETS\ICS\INTERFACE\TPIC2810D.PDF
U109 = SN74AVC2T245RSWR_QFN10: IC DUAL-BIT DUAL SUPPLY BUS TRANSCEIVER QFN10; Chkd/date: SUHAS/031110; Crtd /date: USMAN/130309; Custom_Duty: 15%; Customs_HS_Code: 85423100; Distributor_name: DIGIKEY; Distributor_part_number: 296-23684-1-ND; Height: 0.55MM; Mfr_name: TEXAS INSTRUMENTS; Mistral Part No: 143009030061-R; Package: QFN10; Part_type: ICS\TELECOM\TRANSCEIVER; Project: AXON; RoHS: Sb/ Br FREE; Temperature: -40°C+85°C; Datasheet: Y:\MIS_DATABASE\DATASHEETS\ICS\DIGITAL\BUSTRANSCEIVER\SN74AVC2T245RSWR.PDF
U110 = TCA9555RTWR_WQFN24: IC I/O EXPANDER I2C BUS 16-BIT WQFN24; Chkd/date: USMAN/120913; Crtd /date: VIJAYALAKSHMI/200813; Distributor_name: DIGIKEY; Distributor_part_number: 296-24857-1-ND; Height: 0.80MM; Mfr_name: TEXAS INSTRUMENTS; Mistral Part No: 141013080010-R; Package: WQFN24; Part_type: ICS\DIGITAL\BUSTRANSCEIVER; Project: RTM; RoHS: RoHS; Temperature: -40°C+85°C; Tolerance: NA; Voltage: NA; Wattage: NA; Weight: NA; Datasheet: Y:\MIS_DATABASE\DATASHEETS\ICS\DIGITAL\BUSTRANSCEIVER\TCA9555X.PDF

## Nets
DGND: C26.2 C29.2 C145.2 C147.2 C156.1 C160.2 C161.1 C169.1 C171.1 C295.2 C296.2 C297.2 C298.2 C300.2 C301.2 C309.2 C310.2 C313.2 C314.2 C389.2 C643.2 C644.2 C648.2 C649.2 C658.2 C661.2 C662.2 C672.2 C691.2 C710.2 C715.2 C716.2 C717.2 C718.2 C721.2 C723.2 C725.2 C726.2 FL15.1 J5.1 J5.4 J5.7 J5.8 J5.9 J5.10 J5.13 J5.17 J5.20 J5.23 J5.26 J5.29 J5.32 J5.35 J5.38 J5.41 J5.44 J5.48 J5.51 J5.54 J5.57 J5.60 J5.SH1 J5.SH2 J6.4 J6.5 J6.6 J38.6 J38.7 J38.10 J38.13 J38.16 J38.19 J38.22 J38.25 J38.28 J38.34 Q6.2(S) Q10.2(S) Q11.2(S) Q17.2(S) R39.2 R40.2 R59.2 R60.2 R172.2 R187.1 R190.2 R197.1 R431.1 R453.1 R454.1 R497.2 R659.1 R660.1 R673.2 R680.2 R707.2 R737.1 R738.1 R766.1 R770.2 R771.2 R772.2 R782.2 R784.1 U32.4(GND) U32.9(GND) U32.15(GND) U32.16(GND) U32.21(GND) U32.25(GND) U32.26(GND) U32.32(GND) U32.33(EP) U84.8(~{G}) U84.16(GND) U109.3(GND) U110.9(GND) U110.25(PAD) U113.3(GND) U121.1(GND) U129.1(GND) ; also on sheet 11 12 13 14 15 16 17 18 19 20 21 22 23 24 25 26 27 28 29 30 31 32 33 34 38 39 40 41 42 43 44
VCC1V8: C295.1 C300.1 C662.1 FL4.1 J6.3 U109.6(VCCB) ; also on sheet 11 18 19 20 21 22 23 26 29 31 33 38 41 44
VCC1V8_CLKBUFF: C147.1 C171.2 FL4.2 U32.2(VDDO) U32.6(VDDO) U32.19(VDDO) U32.23(VDDO)
VCC3V3_IO: C26.1 C29.1 C389.1 C658.1 C661.1 C672.1 C723.1 C726.1 FL3.1 J5.18 J5.19 R58.2 R103.1 R104.1 R105.1 R106.1 R107.1 R108.1 R109.1 R110.1 R155.2 R177.2 R224.2 R661.2 R667.2 R672.2 R686.2 R687.1 R698.2 R783.2 U84.1(VCC) U109.7(VCCA) U110.21(VCC) U113.5(VCC) U129.2(IN1) U129.3(IN2) ; also on sheet 11 18 19 20 21 22 23 24 25 26 28 29 30 31 33 34 38 39 41 42 43 44
VCC3V3_OLDI: C648.1 C649.1 C725.1 J38.4 J38.5 U129.6(OUT1) U129.7(OUT2) U129.8(OUT3)
VCC_2V5: C297.1 C298.1 J6.1 ; also on sheet 17 42
VCC_5V0: C309.1 C313.1 C710.1 C721.1 J6.8 J6.10 R754.2 U121.2(IN1) U121.3(IN2) ; also on sheet 30 33 40 44
VCC_12V0: C296.1 C301.1 J6.7 J6.9 ; also on sheet 40 43
VCC_OLDI_5V0: C643.1 C644.1 C715.1 J38.1 J38.2 J38.3 U121.6(OUT1) U121.7(OUT2) U121.8(OUT3)
VDD3V3_CLKBUF: C160.1 C169.2 FL3.2 R173.1 R185.1 R189.2 R193.2 R199.2 U32.10(VDD)
VDD_1V0: C310.1 C314.1 J6.2 ; also on sheet 13 21 22 23 33 42
BOARD ID_LCD_A0: J38.31
BOARD ID_LCD_A2: J38.37
BOARDID_SERDES_A2: J5.11
CDCEL_XIN: R194.2 U32.11(XIN)
CDCEL_XOUT: R191.2 U32.12(XOUT)
CON_LCD_PWR_DN: U110.7(P06) ; also on sheet 44
DDR_VTT_EN: R707.1 U109.4(B2) ; also on sheet 19
DDR_VTT_EN_3V3: U109.9(A2) ; also on sheet 42
ECAP0_IN_APWM0_OUT: J38.38 ; also on sheet 34
GP1_TOUCH_EVT: U110.13(P13) ; also on sheet 44
GPIO_CSI_RESETn: U110.8(P07) ; also on sheet 44
GPIO_eMMC_RSTn: U110.1(P00) ; also on sheet 18
GPIO_MCU_RGMII_RSTN: U110.5(P04) ; also on sheet 23
GPIO_OSPI_RSTn: U110.2(P01) ; also on sheet 19
GPIO_PRG2_RGMII_RESETn: U110.4(P03) ; also on sheet 21
GPIO_SGMII_PHY_INT: J5.46 R58.1 ; also on sheet 34
GPIO_SGMII_PHY_RST: J5.6 R782.1 U110.6(P05)
GPIO_SPI0_RSTn: U110.3(P02) ; also on sheet 19
IN_SEL0: R193.1 R197.2 U32.30(IN_SEL0)
IN_SEL1: R187.2 R189.1 U32.29(IN_SEL1)
LCD_BRD_DET: J38.40 ; also on sheet 20
LCD_BRD_TOUCH_INT: J38.29 ; also on sheet 20
LCD_BRD_TOUCH_RESETn: R686.1 U110.11(P11) U113.1(A)
LCD_DISPLAY_EN: J38.30 R687.2 U110.10(P10)
LCD_SHIELD: FL15.2 J38.SH1 J38.SH2 J38.SH3 J38.SH4
LCD_TOUCH_RESETn: J38.39 R698.1 U113.4(Y)
LED1: LD11.1 U84.3(DRAIN0)
LED2: LD12.1 U84.4(DRAIN1)
LED3: LD13.1 U84.5(DRAIN2)
LED4: LD14.1 U84.6(DRAIN3)
LED5: LD10.1 U84.11(DRAIN4)
LED6: LD15.1 U84.12(DRAIN5)
LED7: LD9.1 U84.13(DRAIN6)
LED8: LD8.1 U84.14(DRAIN7)
MAIN_UART1_SEL: U110.15(P15) ; also on sheet 31
MCU_BOOTMODE0: R225.2 ; also on sheet 25 34
MCU_BOOTMODE1: R548.2 ; also on sheet 25 34
MCU_CLKOUT: R185.2 R190.1 U32.13(PRI_INP) ; also on sheet 34
MCU_RGMII1_CLKIN: R203.2 ; also on sheet 23
MCU_UART_SEL: U109.5(B1) ; also on sheet 31
MCU_UART_SEL_IO_EXP: U109.8(A1) U110.16(P16)
OLDI0_A0N: J38.8 R599.2 U34.J28(OLDI0_A0N)
OLDI0_A0P: J38.9 R599.1 U34.K28(OLDI0_A0P)
OLDI0_A1N: J38.11 R597.2 U34.L27(OLDI0_A1N)
OLDI0_A1P: J38.12 R597.1 U34.K27(OLDI0_A1P)
OLDI0_A2N: J38.14 R595.2 U34.K24(OLDI0_A2N)
OLDI0_A2P: J38.15 R595.1 U34.J24(OLDI0_A2P)
OLDI0_A3N: J38.17 R594.2 U34.J26(OLDI0_A3N)
OLDI0_A3P: J38.18 R594.1 U34.K26(OLDI0_A3P)
OLDI0_CLKN: J38.20 R598.2 U34.L25(OLDI0_CLKN)
OLDI0_CLKP: J38.21 R598.1 U34.K25(OLDI0_CLKP)
OSPI_LBCLKO_GPIO: R705.2 ; also on sheet 19
PCIe0_PRSNTn: J5.21 ; also on sheet 20
PCIE1_ATEST: TP51.1(TP) U34.AC13(RSV9)
PCIe1_PRSNTn: J5.22 ; also on sheet 20
PCIe1_RESREF: R497.1 U34.AC14(SERDES1_REFRES)
PCIE1_SGMII1_RXN1: J5.52 U34.AG9(SERDES1_RXN)
PCIE1_SGMII1_RXP1: J5.53 U34.AH10(SERDES1_RXP)
PCIE1_SGMII1_TXN1: C58.2 J5.50
PCIE1_SGMII1_TXN1_C: C58.1 U34.AH9(SERDES1_TXN)
PCIE1_SGMII1_TXP1: C59.2 J5.49
PCIE1_SGMII1_TXP1_C: C59.1 U34.AG8(SERDES1_TXP)
PCIe_GPIO_RESET_IN: J5.12 R705.1 R743.1
PORz_OUT: J5.30 U113.2(B) ; also on sheet 19 21 25 33 34 44
PRG0_RGMII1_ETH1_CLK: R204.2 ; also on sheet 33
PRG0_RGMII2_ETH2_CLK: R205.2 ; also on sheet 33
PRG1_RGMII1_ETH1_CLK: R206.2 ; also on sheet 33
PRG1_RGMII2_ETH2_CLK: R207.2 ; also on sheet 33
PRG2_ETH_LED0: R464.2 R737.2 ; also on sheet 20
PRG2_ETH_LED1: R458.2 R738.2 ; also on sheet 20
PRG2_MDC: J5.16 ; also on sheet 21 22 29
PRG2_MDIO: J5.15 ; also on sheet 21 22 29
PRG2_RGMII1_ETH1_CLK: R170.2 ; also on sheet 21
PRG2_RGMII2_ETH2_CLK: R169.2 ; also on sheet 22
PRI_INN: C145.1 R172.1 R173.2 U32.14(PRI_INN)
REFCLK0N: J5.58 R60.1 R725.1
REFCLK0N_R: R725.2 U34.AF9(REFCLK0N)
REFCLK0P: J5.59 R59.1 R724.1
REFCLK0P_R: R724.2 U34.AF10(REFCLK0P)
REFCLK1N: J5.27 R40.1 R727.1
REFCLK1N_R: R727.2 U34.AE8(REFCLK1N)
REFCLK1P: J5.28 R39.1 R726.1
REFCLK1P_R: R726.2 U34.AE9(REFCLK1P)
RESET_SoC_MPU: U110.12(P12) ; also on sheet 41
SERDES_BRD_DET: J5.45 ; also on sheet 20
SOC_I2C0_SCL: U84.15(SCL) U110.19(SCL) ; also on sheet 11 33 34 38
SOC_I2C0_SDA: U84.2(SDA) U110.20(SDA) ; also on sheet 11 33 34 38
SOC_I2C1_SCL: J38.26 ; also on sheet 34
SOC_I2C1_SDA: J38.27 ; also on sheet 34
SOC_MCU_SCL: J5.2 ; also on sheet 20 34 44
SOC_MCU_SDA: J5.3 ; also on sheet 20 34 44
SoC_PORz: R743.2 ; also on sheet 34 39
SOC_SERDES_REFCLK0_N: J5.24 ; also on sheet 30
SOC_SERDES_REFCLK0_P: J5.25 ; also on sheet 30
SOC_SERDES_REFCLK1_N: J5.55 U34.AH6(SERDES1_REFCLKN)
SOC_SERDES_REFCLK1_P: J5.56 U34.AH7(SERDES1_REFCLKP)
SOC_SPI1_CLK: J38.32 ; also on sheet 34 38 44
SOC_SPI1_CS0: R675.1 ; also on sheet 34 38
SOC_SPI1_MISO: J38.36 ; also on sheet 34 38 44
SOC_SPI1_MOSI: J38.35 ; also on sheet 34 38 44
SOC_WKUP_SCL: J5.33 J38.23 ; also on sheet 20 33 34 41 44
SOC_WKUP_SDA: J5.34 J38.24 ; also on sheet 20 33 34 41 44
TCA9555_EXP_INT: R661.1 U110.22(~{INT})
USB0_DM: J5.36 ; also on sheet 30
USB0_DP: J5.37 ; also on sheet 30
USB0_DRV_VBUS: J5.5 ; also on sheet 30
USB0_ID_SOC: J5.14 ; also on sheet 30
USB0_PCIE0_SGMII0_RXN0: J5.40 ; also on sheet 30
USB0_PCIE0_SGMII0_RXP0: J5.39 ; also on sheet 30
USB0_PCIE0_SGMII0_TXN0: J5.43 ; also on sheet 30
USB0_PCIE0_SGMII0_TXP0: J5.42 ; also on sheet 30
USB0_VBUS: C691.1 J5.47 ; also on sheet 30
WKUP_OSC0_XIN: R769.2 ; also on sheet 11
WKUP_UART_SEL: U110.14(P14) ; also on sheet 31
N16248811: C716.1 R769.1 R770.1 U32.20(Y7)
N16248833: R169.1 U32.18(Y6)
N16248855: R170.1 U32.17(Y5)
N16248877: R207.1 U32.8(Y4)
N16248899: R206.1 U32.7(Y3)
N16248921: R205.1 U32.5(Y2)
N16248943: R204.1 U32.3(Y1)
N16248965: R203.1 U32.1(Y0)
N17247526: LD11.2 R107.2
N17247539: LD12.2 R108.2
N17247599: LD13.2 R109.2
N17247637: LD14.2 R110.2
N17247662: LD10.2 R106.2
N17247701: LD15.2 R105.2
N17247743: LD9.2 R104.2
N17247786: LD8.2 R103.2
N17248427: R431.2 U84.7(A2)
N17248432: R453.2 U84.10(A1)
N17248439: R454.2 U84.9(A0)
N18184841: R667.1 U110.18(A0)
N18184861: R660.2 U110.23(A1)
N18184865: R659.2 U110.24(A2)
N18320293: C161.2 R192.1 R194.1 Y1.2
N18320301: C156.2 R191.1 R192.2 Y1.1
N18321769: R199.1 U32.31(OE)
N18436285: LD18.1(CATHODE1) Q17.3(D)
N18436298: LD18.3(ANODE) R224.1
N18436321: Q6.1(G) R225.1
N18436342: LD18.2(CATHODE2) Q6.3(D)
N18436344: Q17.1(G) R548.1
N18436628: Q11.1(G) R464.1
N18436656: LD17.2 R177.1
N18436666: LD17.1 Q11.3(D)
N18436681: Q10.1(G) R458.1
N18436707: LD16.2 R155.1
N18860929: R672.1 U109.10(DIR1)
N18860951: R673.1 U109.2(~{OE})
N20141585: R680.1 U109.1(DIR2)
N21124530: J38.33 R675.2
N23010631: LD16.1 Q10.3(D)
N23484157: C717.1 R771.1 U32.24(Y9)
N23484680: C718.1 R772.1 U32.22(Y8)
N23544850: R754.1 U121.5(~{OC})
N23545101: R766.2 U121.4(~{EN})
N23817015: R783.1 U129.5(~{OC})
N23817037: R784.2 U129.4(~{EN})

Not connected (* = marked no-connect by the designer): J5 31*; U32 27(SEC_INN)* 28(SEC_INP)*; U110 17(P17)*

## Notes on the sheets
sheet 35
- SERDES INTERFACE
- SERDES POWER CONNECTOR
- SERDES CONNECTOR
- OLDI INTERFACE
sheet 36
- ETHERNET PHY  CLOCK BUFFER
- REFERENCE INPUT SELECTION
sheet 37
- ETHERNET LED's
- I2C ADDRESS: 0x60
- I2C IO Expander
- PRG2 ETHERNET LED's
- I2C ADDRESS: 0x21
